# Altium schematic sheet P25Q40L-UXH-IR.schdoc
size 127 x 101 mm
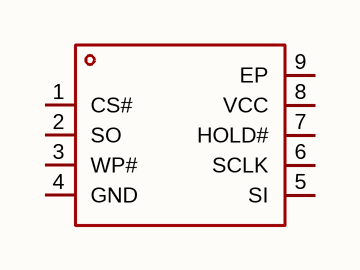
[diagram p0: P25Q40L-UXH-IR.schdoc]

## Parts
U?  p25q40l-uxh-ir  [USON-8_L3.0-W2.0-P0.50-BL-EP_P25XX]  (value not drawn)

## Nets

Not connected (* = marked no-connect by the designer): U? 1(CS#) 2(SO) 3(WP#) 4(GND) 5(SI) 6(SCLK) 7(HOLD#) 8(VCC) 9(EP)

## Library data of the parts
U? = p25q40l-uxh-ir: 接口类型:SPI;存储容量:4Mbit;时钟频率(fc):85MHz;; Manufacturer: PUYA(普冉); AddInBom: yes; ModelId: 12a239e5c7384371915ecb51201bf581; ModelName: USON-8_L3.0-W2.0-H0.6-P0.50; ModelTransform: 118.8974,78.74,0,90,0,0,0,0,0; Interface: SPI; Memory Size: 4Mbit; Clock Frequency: 85MHz; Voltage - Supply: 1.65V~2V; Standby Supply Current: 9uA; Program / Erase Cycles: 100000次; Page Programming Time (Tpp): 2ms; Block Erase Time(tBE): 8ms@(32KB); Data Retention - TDR (Year): 20年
